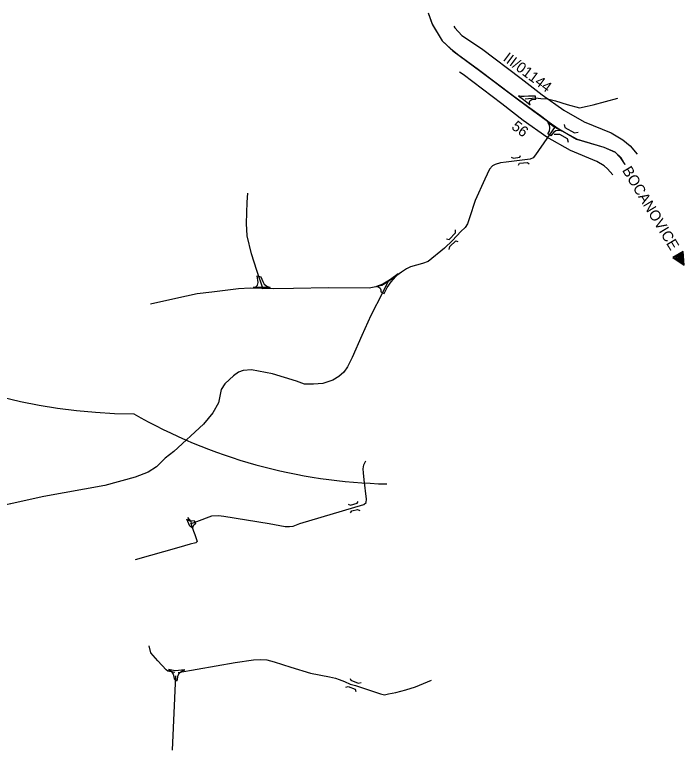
# Model space of a CAD drawing. Extents: x -444937 to -436355, y -1135022 to -1129798.
# Drawn here: x -441751 to -441120, y -1132642 to -1131949 of the extents above; entities that cross this region are included whole.
import ezdxf

# ---------------------------------------------------------------- set-up
doc = ezdxf.new("R2010")
doc.units = 0
for name, color, linetype in [('01_PARC_VNEJSI', 7, 'Continuous'), ('04_PARC_VNITRNI', 7, 'Continuous'), ('Vrstva 7', 7, 'Continuous'), ('Vrstva 75', 7, 'Continuous'), ('Vrstva 8', 7, 'Continuous'), ('Vrstva 84', 7, 'Continuous')]:
    doc.layers.add(name, color=color, linetype=linetype)

msp = doc.modelspace()

# ---------------------------------------------------------------- linework, layer by layer
at = {"layer": '01_PARC_VNEJSI'}
for centre, start, end in [((-441638.38, -1131824.9), 205.14125, 269.91178), ((-441390.5, -1131891.11), 240.17849, 268.81846)]:
    msp.add_arc(centre, 500, start, end, dxfattribs=at)
at = {"layer": '04_PARC_VNITRNI'}
for points in [[(-441337.66, -1131959.86), (-441336.59, -1131961.55), (-441329.85, -1131968.54), (-441311.37, -1131981.07), (-441274.26, -1132009.22), (-441254.45, -1132024.44), (-441233.88, -1132038.95), (-441214.75, -1132049.92), (-441189.45, -1132060.49), (-441178.41, -1132066.91), (-441171.49, -1132072.75), (-441164.95, -1132080.35)], [(-441187.71, -1132099.9), (-441192.66, -1132094.13), (-441195.76, -1132091.53), (-441202.83, -1132087.41), (-441227.75, -1132077.05), (-441250.02, -1132064.28), (-441272.24, -1132048.6), (-441292.47, -1132033.06), (-441328.87, -1132005.45), (-441332.27, -1132003.15)]]:
    msp.add_lwpolyline(points, dxfattribs=at)
at = {"layer": 'Vrstva 7'}
msp.add_lwpolyline([(-441361.7, -1131947.32), (-441358.1, -1131958.1), (-441348.47, -1131973.62), (-441338.59, -1131983.11), (-441311.96, -1132002.71), (-441279, -1132027.38), (-441268.13, -1132035.4), (-441250.5, -1132048.41), (-441236.51, -1132058.11), (-441221.25, -1132066.26), (-441196.14, -1132073.95), (-441185.83, -1132078.16), (-441180.75, -1132083.44), (-441176.33, -1132090.13)], dxfattribs=at)
for points in [[(-441120.42, -1132184.97), (-441121.41, -1132172.13), (-441131.09, -1132177.76)], [(-441121.35, -1132183.38), (-441122.11, -1132173.46), (-441129.59, -1132177.81)], [(-441122.27, -1132181.79), (-441122.81, -1132174.8), (-441128.08, -1132177.86)], [(-441123.2, -1132180.2), (-441123.51, -1132176.13), (-441126.58, -1132177.91)], [(-441124.12, -1132178.61), (-441124.21, -1132177.46), (-441125.08, -1132177.96)]]:
    msp.add_lwpolyline(points, close=True, dxfattribs=at)
at = {"layer": 'Vrstva 75'}
msp.add_lwpolyline([(-441361.7, -1131947.32), (-441357.55, -1131958.65), (-441348.47, -1131973.62), (-441340.75, -1131980.98), (-441334.18, -1131986.32), (-441314.19, -1132000.74), (-441282.12, -1132024.79), (-441271.55, -1132032.65), (-441255.99, -1132044.11), (-441242.54, -1132054.35), (-441221.84, -1132066.21), (-441196.14, -1132073.95), (-441185.42, -1132078.46), (-441180.16, -1132083.44), (-441176.33, -1132090.13)], dxfattribs=at)
at = {"layer": 'Vrstva 8'}
msp.add_line((-441602.74, -1132641.88), (-441599.44, -1132571.75), dxfattribs=at)
for points in [[(-441272.06, -1132028.95), (-441265.55, -1132033.96), (-441266.21, -1132032.52), (-441266.21, -1132031.3), (-441265.54, -1132029.95), (-441263.96, -1132028.89), (-441260.36, -1132028.6), (-441260.56, -1132025.71), (-441267.31, -1132025.71), (-441271.34, -1132026.2), (-441274.2, -1132026.16), (-441276.59, -1132025.47)], [(-441246.01, -1132063.22), (-441248.89, -1132061.23), (-441247.54, -1132058.64), (-441247.12, -1132055.49), (-441247.33, -1132052.76), (-441248.94, -1132050.16), (-441242.25, -1132054.88), (-441236.23, -1132058.33), (-441238.84, -1132058.09), (-441241.36, -1132058.6), (-441243.59, -1132059.94)], [(-441526.57, -1132206.08), (-441524.05, -1132205.39), (-441522.47, -1132203.85), (-441521.93, -1132201.46), (-441522.69, -1132195.04), (-441519.37, -1132196.09), (-441517.59, -1132200.46), (-441516.13, -1132202.81), (-441513.75, -1132204.77), (-441510.54, -1132206.01)], [(-441410.41, -1132205.23), (-441408.42, -1132205.5), (-441406.92, -1132206.71), (-441406.41, -1132208.21), (-441406.42, -1132210.18), (-441403.23, -1132211.61), (-441400.35, -1132206.02), (-441396.61, -1132200.54), (-441389.92, -1132193.17), (-441395.95, -1132197.42), (-441399.85, -1132200.07), (-441404.51, -1132202.95)], [(-441589.13, -1132424.28), (-441587.96, -1132425.19), (-441586.34, -1132425.67), (-441584.56, -1132425.76), (-441582.08, -1132425.39), (-441580.87, -1132428.67), (-441582.06, -1132429.45), (-441582.78, -1132430.14), (-441583.32, -1132431.3), (-441583.63, -1132432.49), (-441586.16, -1132430.77)], [(-441606.28, -1132565.86), (-441603.82, -1132567.4), (-441601.92, -1132570.05), (-441601.4, -1132572.3), (-441601.14, -1132574.44), (-441598.23, -1132576.37), (-441597.13, -1132571.26), (-441595.92, -1132568.95), (-441593.85, -1132567.22), (-441591.07, -1132566.09), (-441600.14, -1132567.02)]]:
    msp.add_lwpolyline(points, close=True, dxfattribs=at)
for points in [[(-441270.36, -1132028.42), (-441260.57, -1132027.47), (-441255.5, -1132028.04), (-441249.17, -1132028.32), (-441241.88, -1132030.17), (-441230.89, -1132033.55), (-441219.13, -1132036.9), (-441211.99, -1132035.28), (-441206.21, -1132033.89), (-441183.12, -1132027.68)], [(-441241.95, -1132054.31), (-441260.52, -1132081.21), (-441262.79, -1132083.85), (-441265.53, -1132085.27), (-441273.08, -1132086.13), (-441288.31, -1132087.92), (-441293.7, -1132088.49), (-441298.71, -1132090.09), (-441300.98, -1132091.42), (-441303.81, -1132094.44), (-441308.21, -1132104.11), (-441317.43, -1132124.17), (-441322.77, -1132140.31), (-441324.59, -1132145.92), (-441326.73, -1132149.55), (-441331.02, -1132153.34), (-441338.93, -1132161.75), (-441346.18, -1132169.01), (-441361.65, -1132181.66), (-441367.1, -1132183.33), (-441378.28, -1132186.52), (-441382.09, -1132188.54), (-441386.87, -1132191.57), (-441399.69, -1132200.6), (-441405.29, -1132204.07), (-441412.54, -1132205.65), (-441417.16, -1132206.51), (-441455.74, -1132206.49), (-441488.51, -1132206.94), (-441507.71, -1132207.24), (-441529.54, -1132206.58), (-441540.29, -1132207.21), (-441565.42, -1132210.34), (-441579.26, -1132212.11), (-441599.51, -1132216.47), (-441623.33, -1132221.72)], [(-441517.14, -1132207.55), (-441523.11, -1132189.91), (-441528.05, -1132174.41), (-441532.34, -1132157.26), (-441533, -1132145.72), (-441532.34, -1132125.6), (-441531.68, -1132117.06)], [(-441399.69, -1132200.6), (-441404.82, -1132210.89), (-441415.7, -1132232.33), (-441424.27, -1132251.13), (-441433.3, -1132272.03), (-441437.66, -1132280.79), (-441441.15, -1132285.85), (-441445.95, -1132289.94), (-441451.61, -1132293.26), (-441460.81, -1132296.31), (-441469.89, -1132297.02), (-441478.12, -1132296.95), (-441485.89, -1132294.15), (-441508.29, -1132287.43), (-441528.21, -1132283.57), (-441535.87, -1132284.21), (-441540.48, -1132285.85), (-441545.15, -1132289.13), (-441548.87, -1132292.6), (-441553.34, -1132296.85), (-441556.62, -1132302.11), (-441559.27, -1132314.5), (-441564.44, -1132324.04), (-441573.53, -1132334.68), (-441601.42, -1132360.57), (-441609.42, -1132366.88), (-441617.57, -1132374.87), (-441625.48, -1132379.81), (-441637.68, -1132384.66), (-441666.36, -1132392.57), (-441723.77, -1132403), (-441786.73, -1132416.52)], [(-441585.59, -1132428.61), (-441579.74, -1132426.38), (-441565.63, -1132420.93), (-441559.37, -1132420.66), (-441554.27, -1132421.3), (-441511.47, -1132428.43), (-441496.53, -1132431.19), (-441492.25, -1132431.13), (-441488.83, -1132430.89), (-441482.56, -1132428.43), (-441422.31, -1132410.29), (-441420.08, -1132408.44), (-441419.7, -1132405.29), (-441421.94, -1132387.27), (-441422.76, -1132380.55), (-441422.9, -1132376.85), (-441422.35, -1132373.15), (-441420.57, -1132369.32)], [(-441588.4, -1132422.57), (-441585.24, -1132426.43), (-441584.73, -1132430.16), (-441582.78, -1132435.46), (-441581.68, -1132438.6), (-441579.36, -1132445.39), (-441580.54, -1132446.4), (-441586.07, -1132447.69), (-441596.77, -1132450.97), (-441637.67, -1132462.44)], [(-441600.53, -1132568.72), (-441606.87, -1132567.3), (-441608.43, -1132565.97), (-441616.44, -1132557.55), (-441623.11, -1132550.12), (-441624.65, -1132543.61)], [(-441597.11, -1132568.71), (-441543.66, -1132559.33), (-441526.38, -1132556.59), (-441519.55, -1132556.26), (-441513.86, -1132556.76), (-441506.86, -1132558.44), (-441490.98, -1132563.47), (-441472.65, -1132569.1), (-441454.67, -1132572.64), (-441448.99, -1132574.08), (-441445.5, -1132575.21), (-441440.62, -1132577.21), (-441435.22, -1132579.56), (-441430.04, -1132580.75), (-441406.59, -1132588.7), (-441402.91, -1132589.76), (-441398.94, -1132588.77), (-441392.11, -1132587.32), (-441382.72, -1132585.03), (-441373.59, -1132582.24), (-441358.56, -1132575.72)]]:
    msp.add_lwpolyline(points, dxfattribs=at)
at = {"layer": 'Vrstva 84'}
for points in [[(-441233.45, -1132052.51), (-441232.83, -1132055.28), (-441223.75, -1132060.36), (-441220.43, -1132059.59)], [(-441242.88, -1132061.63), (-441238.03, -1132061.71), (-441230.79, -1132065.63), (-441229.71, -1132069.17)], [(-441283.44, -1132083.18), (-441281.29, -1132084.18), (-441275.35, -1132083.33), (-441274.72, -1132081.84)], [(-441276.66, -1132090.74), (-441275.58, -1132089.03), (-441268.27, -1132088.37), (-441266.49, -1132089.67)], [(-441344.32, -1132160.25), (-441342.04, -1132160.71), (-441336.06, -1132154.48), (-441335.99, -1132151.71)], [(-441341.95, -1132170.38), (-441341.45, -1132167.36), (-441335.73, -1132162.17), (-441333.84, -1132162.84)], [(-441437.01, -1132409.98), (-441434.81, -1132411), (-441428.49, -1132409.26), (-441427.67, -1132407.46)], [(-441434.94, -1132418.24), (-441433.56, -1132416.44), (-441428.27, -1132415.16), (-441426.01, -1132415.98)], [(-441435.36, -1132574.29), (-441434.49, -1132575.93), (-441427.77, -1132578.65), (-441424.79, -1132577.93)], [(-441439.21, -1132582.3), (-441437.11, -1132581.68), (-441430.38, -1132584.4), (-441429.77, -1132586.51)]]:
    msp.add_lwpolyline(points, dxfattribs=at)

# ---------------------------------------------------------------- texts
at = {"layer": 'Vrstva 7'}
for s, rotation, p in [('III/01144', 323.33947, (-441291.88, -1131991.76)), ('BOCANOVICE', 301.13022, (-441179.3, -1132095.6))]:
    msp.add_text(s, height=10, rotation=rotation, dxfattribs=at).set_placement(p)
at = {"layer": 'Vrstva 75'}
msp.add_text('56', height=10, rotation=322.46185, dxfattribs=at).set_placement((-441283.97, -1132055.98))

doc.saveas('drawing.dxf')
